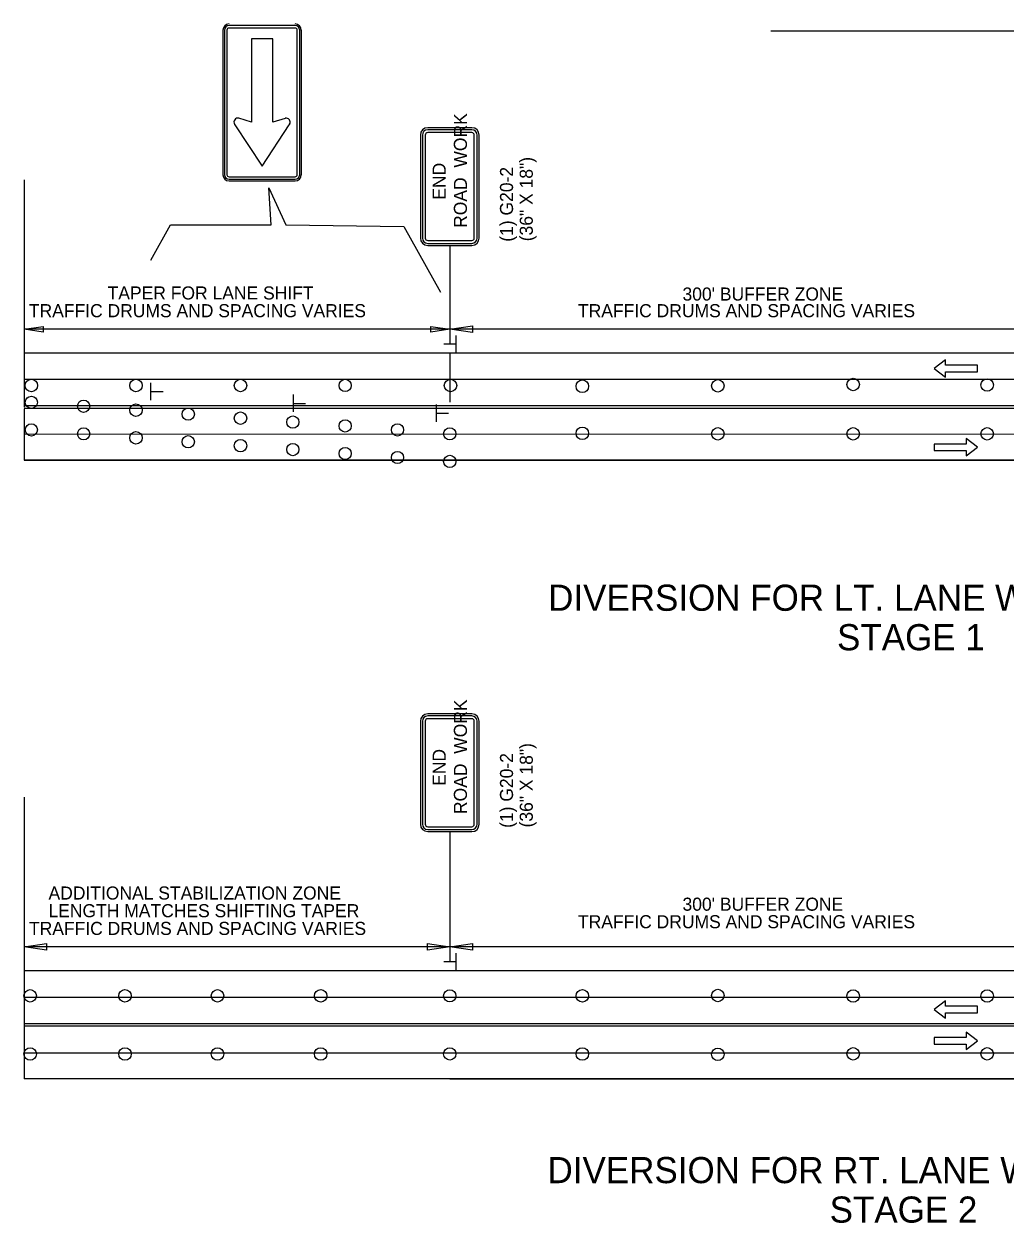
# Model space of a CAD drawing. Extents: x 1930579 to 1938013, y 596452 to 597673.
# Drawn here: x 1933682 to 1934133, y 596636 to 597187 of the extents above; entities that cross this region are included whole.
import ezdxf

# ---------------------------------------------------------------- set-up
doc = ezdxf.new("R2010")
doc.units = 0
for name, color, linetype in [('Default', 7, 'Continuous'), ('P_TC_Signs_Permanent', 7, 'Continuous'), ('P_TC_Signs_Temporary', 7, 'Continuous'), ('R_Border', 7, 'Continuous'), ('R_Striping', 7, 'Continuous')]:
    doc.layers.add(name, color=color, linetype=linetype)

msp = doc.modelspace()

# ---------------------------------------------------------------- linework, layer by layer
at = {"layer": 'Default'}
for p, q in [((1934025.15, 597183.38), (1934153.46, 597183.38)), ((1933682.42, 597114.97), (1933682.42, 597010.74)), ((1933877.75, 597057.24), (1933877.75, 597041.13)), ((1933682.42, 597046.45), (1933691.12, 597047.75)), ((1933691.12, 597047.75), (1933691.12, 597045.15)), ((1933869.06, 597045.15), (1933869.06, 597047.75)), ((1933869.06, 597047.75), (1933877.75, 597046.45)), ((1933877.84, 597046.45), (1933888.14, 597048)), ((1933888.14, 597048), (1933888.14, 597044.9)), ((1933877.75, 597046.45), (1933682.42, 597046.45)), ((1933691.12, 597045.15), (1933682.42, 597046.45)), ((1933877.75, 597046.45), (1933869.06, 597045.15)), ((1934186.36, 597046.45), (1933877.75, 597046.45)), ((1933888.14, 597044.9), (1933877.84, 597046.45)), ((1933880.6, 597043.56), (1933880.6, 597035.58)), ((1933880.48, 597039.59), (1933875.03, 597039.59)), ((1934686.11, 597035.46), (1933682.42, 597035.46)), ((1933877.75, 597035.77), (1933877.75, 597012.95)), ((1933682.42, 597023.46), (1934686.11, 597023.46)), ((1933740.62, 597013.87), (1933740.62, 597021.85)), ((1933740.74, 597017.84), (1933746.18, 597017.84)), ((1933806.03, 597008.46), (1933806.03, 597016.44)), ((1934686.11, 597011.23), (1933682.42, 597011.23)), ((1934686.11, 597010.08), (1933682.42, 597010.08)), ((1933682.42, 597009.88), (1933682.42, 596986.31)), ((1933806.15, 597012.42), (1933811.6, 597012.42)), ((1933871.6, 597003.94), (1933871.6, 597011.92)), ((1933871.71, 597007.91), (1933877.16, 597007.91)), ((1933682.42, 596998.31), (1934686.11, 596998.53)), ((1933682.42, 596986.31), (1933962.94, 596986.31)), ((1934686.11, 596986.31), (1933682.42, 596986.31)), ((1933947.06, 596986.31), (1934222.13, 596986.31)), ((1933682.42, 596831.73), (1933682.42, 596726.82)), ((1933877.75, 596773.75), (1933877.75, 596757.64)), ((1933682.42, 596762.96), (1933692.73, 596764.51)), ((1933877.84, 596762.96), (1933682.42, 596762.96)), ((1933692.73, 596761.41), (1933682.42, 596762.96)), ((1933692.73, 596764.51), (1933692.73, 596761.41)), ((1933867.54, 596761.41), (1933867.54, 596764.51)), ((1933867.54, 596764.51), (1933877.84, 596762.96)), ((1933877.84, 596762.96), (1933867.54, 596761.41)), ((1934186.36, 596762.96), (1933877.75, 596762.96)), ((1933877.84, 596762.96), (1933888.14, 596764.51)), ((1933888.14, 596761.41), (1933877.84, 596762.96)), ((1933888.14, 596764.51), (1933888.14, 596761.41)), ((1933880.48, 596756.1), (1933875.03, 596756.1)), ((1933880.6, 596760.07), (1933880.6, 596752.09)), ((1934686.11, 596751.97), (1933682.42, 596751.97)), ((1933682.42, 596739.97), (1934686.11, 596739.97)), ((1934686.11, 596727.74), (1933682.42, 596727.74)), ((1933682.42, 596726.82), (1933682.42, 596702.39)), ((1934686.11, 596726.59), (1933682.42, 596726.59)), ((1933682.42, 596714.39), (1934686.11, 596714.39)), ((1934686.11, 596702.39), (1933682.42, 596702.39)), ((1933877.75, 596702.39), (1933962.94, 596702.39)), ((1933947.06, 596702.39), (1934222.13, 596702.39))]:
    msp.add_line(p, q, dxfattribs=at)
for centre, radius in [((1933685.74, 597020.59), 2.87), ((1933733.75, 597020.59), 2.87), ((1933781.75, 597020.59), 2.87), ((1933829.75, 597020.65), 2.81), ((1933878.08, 597020.59), 2.87), ((1933938.61, 597020.27), 2.87), ((1934000.75, 597020.48), 2.87), ((1934062.89, 597021.09), 2.87), ((1934124.37, 597020.86), 2.87), ((1933685.74, 597012.89), 2.81), ((1933709.75, 597011.08), 2.81), ((1933733.75, 597009.27), 2.87), ((1933757.75, 597007.46), 2.81), ((1933781.75, 597005.65), 2.87), ((1933685.74, 597000.24), 2.81), ((1933805.75, 597003.84), 2.81), ((1933829.75, 597002.04), 2.81), ((1933853.75, 597000.23), 2.81), ((1933709.75, 596998.43), 2.81), ((1933733.75, 596996.62), 2.87), ((1933757.75, 596994.81), 2.81), ((1933877.75, 596998.42), 2.81), ((1933938.61, 596998.65), 2.87), ((1934000.75, 596998.42), 2.87), ((1934062.89, 596998.42), 2.87), ((1934124.37, 596998.42), 2.87), ((1933781.75, 596993), 2.87), ((1933805.75, 596991.19), 2.81), ((1933829.75, 596989.39), 2.81), ((1933853.75, 596987.58), 2.81), ((1933877.75, 596985.77), 2.81), ((1933685.23, 596740.51), 2.87), ((1933728.72, 596740.51), 2.87), ((1933771.19, 596740.51), 2.87), ((1933818.54, 596740.51), 2.87), ((1933877.75, 596740.51), 2.81), ((1933938.61, 596740.51), 2.87), ((1934000.75, 596740.66), 2.87), ((1934062.89, 596740.45), 2.87), ((1934124.37, 596740.44), 2.87), ((1934124.37, 596713.91), 2.87), ((1933685.23, 596713.84), 2.87), ((1933728.72, 596713.84), 2.87), ((1933771.19, 596713.84), 2.87), ((1933818.54, 596713.84), 2.87), ((1933877.75, 596713.84), 2.81), ((1933938.61, 596713.84), 2.87), ((1934000.75, 596713.69), 2.87), ((1934062.89, 596713.9), 2.87)]:
    msp.add_circle(centre, radius, dxfattribs=at)
at = {"layer": 'P_TC_Signs_Permanent'}
for p, q in [((1933806.82, 597185.77), (1933776.45, 597185.77)), ((1933806.82, 597184.65), (1933776.45, 597184.65)), ((1933773.64, 597183.71), (1933773.64, 597117.33)), ((1933774.39, 597183.71), (1933774.39, 597117.33)), ((1933775.51, 597183.71), (1933775.51, 597117.33)), ((1933807.76, 597117.33), (1933807.76, 597183.71)), ((1933808.89, 597117.33), (1933808.89, 597183.71)), ((1933809.64, 597117.33), (1933809.64, 597183.71)), ((1933776.45, 597116.4), (1933806.82, 597116.4)), ((1933776.45, 597115.27), (1933806.82, 597115.27)), ((1933776.45, 597114.52), (1933806.82, 597114.52))]:
    msp.add_line(p, q, dxfattribs=at)
for points in [[(1933802.27, 597143.22), (1933796.51, 597141.5), (1933796.51, 597179.77), (1933786.76, 597179.77), (1933786.76, 597141.5), (1933781.01, 597143.26)], [(1933779.19, 597140.26), (1933791.64, 597121.27), (1933804.04, 597140.27)]]:
    msp.add_lwpolyline(points, dxfattribs=at)
for centre, radius, start, end in [((1933776.45, 597183.71), 2.81, 90, 180), ((1933776.45, 597183.71), 2.06, 90, 180), ((1933776.45, 597183.71), 0.938, 90, 180), ((1933806.82, 597183.71), 2.81, 360, 90), ((1933806.82, 597183.71), 2.06, 360, 90), ((1933806.82, 597183.71), 0.937, 360, 90), ((1933780.52, 597141.53), 1.8, 74.0309, 213.4755), ((1933716.46, 597099.16), 75, 33.2286, 33.4755), ((1933802.75, 597141.53), 1.76, 326.5994, 105.9691), ((1933866.84, 597099.27), 75, 146.5994, 146.857), ((1933776.45, 597117.33), 2.81, 180, 270), ((1933776.45, 597117.33), 2.06, 180, 270), ((1933776.45, 597117.33), 0.938, 180, 270), ((1933806.82, 597117.33), 2.81, 270, 360), ((1933806.82, 597117.33), 2.06, 270, 360), ((1933806.82, 597117.33), 0.938, 270, 360)]:
    msp.add_arc(centre, radius, start, end, dxfattribs=at)
at = {"layer": 'P_TC_Signs_Temporary'}
for p, q in [((1933864.25, 597135.53), (1933864.25, 597088.28)), ((1933865.19, 597135.53), (1933865.19, 597088.28)), ((1933866.5, 597135.53), (1933866.5, 597088.28)), ((1933887.88, 597138.91), (1933867.63, 597138.91)), ((1933887.88, 597137.97), (1933867.63, 597137.97)), ((1933887.88, 597136.66), (1933867.63, 597136.66)), ((1933889, 597088.28), (1933889, 597135.53)), ((1933890.32, 597088.28), (1933890.32, 597135.53)), ((1933891.25, 597088.28), (1933891.25, 597135.53)), ((1933867.63, 597087.16), (1933887.88, 597087.16)), ((1933867.63, 597085.85), (1933887.88, 597085.85)), ((1933867.63, 597084.91), (1933887.88, 597084.91)), ((1933864.25, 596866.53), (1933864.25, 596819.28)), ((1933865.19, 596866.53), (1933865.19, 596819.28)), ((1933866.5, 596866.53), (1933866.5, 596819.28)), ((1933887.88, 596869.9), (1933867.63, 596869.9)), ((1933887.88, 596868.97), (1933867.63, 596868.97)), ((1933887.88, 596867.65), (1933867.63, 596867.65)), ((1933889, 596819.28), (1933889, 596866.53)), ((1933890.32, 596819.28), (1933890.32, 596866.53)), ((1933891.25, 596819.28), (1933891.25, 596866.53)), ((1933867.63, 596818.15), (1933887.88, 596818.15)), ((1933867.63, 596816.84), (1933887.88, 596816.84)), ((1933867.63, 596815.9), (1933887.88, 596815.9))]:
    msp.add_line(p, q, dxfattribs=at)
for centre, radius, start, end in [((1933867.63, 597135.53), 3.38, 90, 180), ((1933867.63, 597135.53), 2.44, 90, 180), ((1933867.63, 597135.53), 1.13, 90, 180), ((1933887.88, 597135.53), 3.37, 360, 90), ((1933887.88, 597135.53), 2.44, 360, 90), ((1933887.88, 597135.53), 1.13, 360, 90), ((1933867.63, 597088.28), 3.37, 180, 270), ((1933867.63, 597088.28), 2.44, 180, 270), ((1933867.63, 597088.28), 1.13, 180, 270), ((1933887.88, 597088.28), 2.44, 270, 360), ((1933887.88, 597088.28), 1.13, 270, 360), ((1933887.88, 597088.28), 3.38, 270, 360), ((1933867.63, 596866.53), 3.38, 90, 180), ((1933867.63, 596866.53), 2.44, 90, 180), ((1933867.63, 596866.53), 1.13, 90, 180), ((1933887.88, 596866.53), 3.37, 360, 90), ((1933887.88, 596866.53), 2.44, 360, 90), ((1933887.88, 596866.53), 1.13, 360, 90), ((1933867.63, 596819.28), 3.37, 180, 270), ((1933867.63, 596819.28), 2.44, 180, 270), ((1933867.63, 596819.28), 1.13, 180, 270), ((1933887.88, 596819.28), 2.44, 270, 360), ((1933887.88, 596819.28), 1.13, 270, 360), ((1933887.88, 596819.28), 3.38, 270, 360)]:
    msp.add_arc(centre, radius, start, end, dxfattribs=at)
at = {"layer": 'R_Border'}
for p, q in [((1933877.75, 597084.91), (1933877.75, 597039.75)), ((1933877.75, 596815.9), (1933877.75, 596756.1))]:
    msp.add_line(p, q, dxfattribs=at)
msp.add_lwpolyline([(1933740.62, 597078.12), (1933749.63, 597094.42), (1933795.86, 597094.42), (1933794.66, 597111.31), (1933802.46, 597094.42), (1933856.66, 597093.63), (1933873.54, 597063.48)], dxfattribs=at)
at = {"layer": 'R_Striping'}
for points in [[(1934105.16, 597032.39), (1934099.97, 597028.39), (1934105.16, 597024.39), (1934105.16, 597026.89), (1934119.87, 597026.89), (1934119.87, 597029.89), (1934105.16, 597029.89)], [(1934114.68, 596988.26), (1934119.87, 596992.26), (1934114.68, 596996.26), (1934114.68, 596993.76), (1934099.97, 596993.76), (1934099.97, 596990.76), (1934114.68, 596990.76)], [(1934105.16, 596738.27), (1934099.97, 596734.27), (1934105.16, 596730.27), (1934105.16, 596732.77), (1934119.87, 596732.77), (1934119.87, 596735.77), (1934105.16, 596735.77)], [(1934114.68, 596715.86), (1934119.87, 596719.86), (1934114.68, 596723.86), (1934114.68, 596721.36), (1934099.97, 596721.36), (1934099.97, 596718.36), (1934114.68, 596718.36)]]:
    msp.add_lwpolyline(points, close=True, dxfattribs=at)

# ---------------------------------------------------------------- texts
at = {"layer": 'Default'}
for s, height, p in [('TAPER FOR LANE SHIFT', 6, (1933720.74, 597060.08)), ("300' BUFFER ZONE", 6, (1933984.55, 597059.59)), ('TRAFFIC DRUMS AND SPACING VARIES', 6, (1933684.61, 597051.95)), ('TRAFFIC DRUMS AND SPACING VARIES', 6, (1933936.58, 597051.95)), ('DIVERSION FOR LT. LANE WORK ZONE', 12, (1933922.91, 596917.22)), ('STAGE 1', 12, (1934055.48, 596899.1)), ('ADDITIONAL STABILIZATION ZONE', 6, (1933693.63, 596784.71)), ("300' BUFFER ZONE", 6, (1933984.55, 596779.58)), ('LENGTH MATCHES SHIFTING TAPER', 6, (1933693.6, 596776.59)), ('TRAFFIC DRUMS AND SPACING VARIES', 6, (1933936.58, 596771.54)), ('TRAFFIC DRUMS AND SPACING VARIES', 6, (1933684.66, 596768.46)), ('DIVERSION FOR RT. LANE WORK ZONE', 12, (1933922.63, 596654.55)), ('STAGE 2', 12, (1934052.08, 596636.43))]:
    msp.add_text(s, height=height, rotation=360, dxfattribs=at).set_placement(p)
at = {"layer": 'P_TC_Signs_Temporary'}
for s, p in [('ROAD  WORK', (1933885.63, 597092.95)), ('END', (1933875.88, 597105.88)), ('ROAD  WORK', (1933885.63, 596823.94)), ('END', (1933875.88, 596836.87))]:
    msp.add_text(s, height=6, rotation=90, dxfattribs=at).set_placement(p)
at = {"layer": 'R_Border'}
for s, p in [('(36" X 18")', (1933915.85, 597086.8)), ('(1) G20-2', (1933906.79, 597086.59)), ('(36" X 18")', (1933915.85, 596817.8)), ('(1) G20-2', (1933906.79, 596817.59))]:
    msp.add_text(s, height=6, rotation=90, dxfattribs=at).set_placement(p)

doc.saveas('drawing.dxf')
